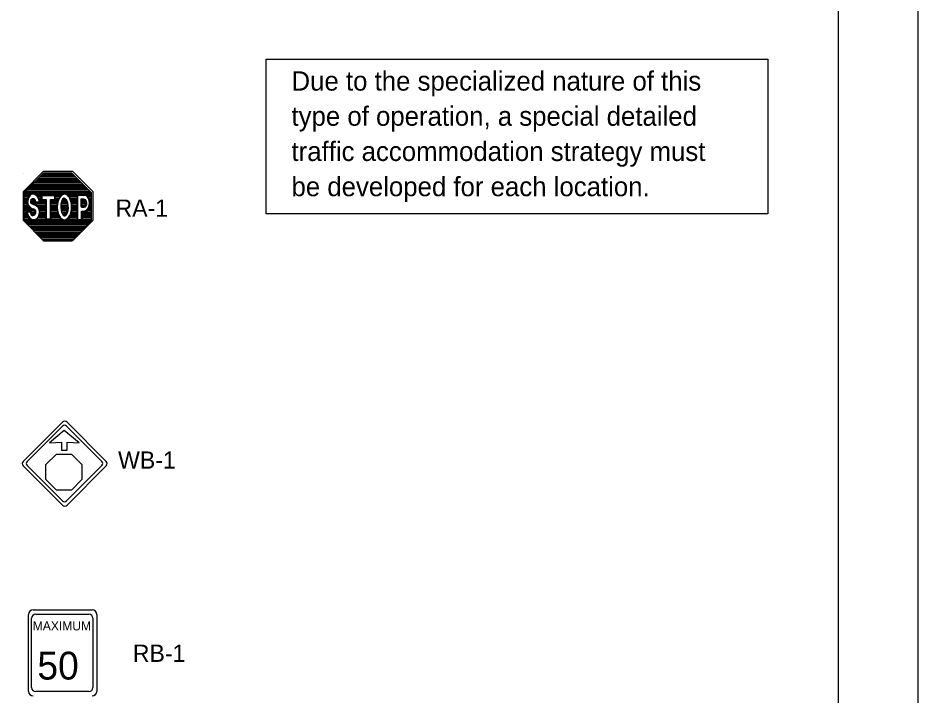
# Model space of a CAD drawing. Extents: x 1361 to 1577, y 123 to 402.
# Drawn here: x 1464.1 to 1577.1, y 208.6 to 293.6 of the extents above; entities that cross this region are included whole.
import ezdxf

# ---------------------------------------------------------------- set-up
doc = ezdxf.new("R2010")
doc.units = 0
for name, color, linetype in [('Level 10', 7, 'Continuous'), ('Level 44', 7, 'Continuous'), ('Level 60', 7, 'Continuous')]:
    doc.layers.add(name, color=color, linetype=linetype)

msp = doc.modelspace()

# ---------------------------------------------------------------- linework, layer by layer
at = {"layer": 'Level 10'}
for points in [[(1495.3, 288.49), (1558.27, 288.49), (1558.27, 269.05), (1495.3, 269.05)], [(1468.97, 238.93), (1470.85, 238.93), (1472.17, 237.6), (1472.17, 235.73), (1470.85, 234.41), (1468.97, 234.41), (1467.65, 235.73), (1467.65, 237.6)]]:
    msp.add_lwpolyline(points, close=True, dxfattribs=at)
at = {"layer": 'Level 44'}
for p, q in [((1467.36, 274.16), (1464.88, 271.69)), ((1464.88, 274.16), (1464.88, 274.16)), ((1470.88, 274.16), (1467.36, 274.16)), ((1473.35, 271.69), (1470.88, 274.16)), ((1464.88, 271.69), (1464.88, 268.17)), ((1467.06, 270.82), (1467.06, 271.38)), ((1467.06, 271.38), (1468.76, 271.38)), ((1467.12, 271.42), (1467.12, 270.88)), ((1468.76, 271.42), (1467.12, 271.42)), ((1468.76, 270.86), (1468.76, 271.42)), ((1468.76, 271.38), (1468.76, 270.81)), ((1469.96, 271.52), (1469.98, 271.52)), ((1472.44, 271.45), (1471.58, 271.45)), ((1471.58, 271.45), (1471.58, 268.35)), ((1471.66, 268.22), (1471.66, 271.41)), ((1471.66, 271.41), (1472.55, 271.41)), ((1473.35, 268.17), (1473.35, 271.69)), ((1466.8, 270.49), (1466.26, 270.49)), ((1466.86, 270.55), (1466.33, 270.55)), ((1467.65, 270.82), (1467.06, 270.82)), ((1467.12, 270.88), (1467.69, 270.88)), ((1467.65, 268.31), (1467.65, 270.82)), ((1467.69, 270.88), (1467.69, 268.44)), ((1468.76, 270.81), (1468.2, 270.81)), ((1468.2, 270.81), (1468.2, 268.31)), ((1468.22, 268.44), (1468.22, 270.86)), ((1468.22, 270.86), (1468.76, 270.86)), ((1469.94, 270.98), (1469.96, 270.99)), ((1472.36, 270.89), (1472.03, 270.89)), ((1472.03, 270.89), (1472.03, 269.99)), ((1472.03, 270.89), (1472.03, 269.99)), ((1472.36, 270.89), (1472.03, 270.89)), ((1472.12, 270.84), (1472.12, 269.91)), ((1472.47, 270.84), (1472.12, 270.84)), ((1472.47, 270.84), (1472.12, 270.84)), ((1472.12, 270.84), (1472.12, 269.91)), ((1465.18, 269.34), (1465.68, 269.34)), ((1465.29, 269.44), (1465.78, 269.44)), ((1472.03, 269.99), (1472.36, 269.99)), ((1472.03, 269.99), (1472.36, 269.99)), ((1472.09, 268.35), (1472.09, 269.41)), ((1472.09, 269.41), (1472.41, 269.41)), ((1472.12, 269.91), (1472.46, 269.91)), ((1472.12, 269.91), (1472.46, 269.91)), ((1472.19, 269.31), (1472.52, 269.31)), ((1472.19, 269.31), (1472.19, 268.22)), ((1472.51, 269.31), (1472.19, 269.31)), ((1464.88, 268.17), (1467.36, 265.69)), ((1465.34, 268.71), (1465.34, 268.71)), ((1468.2, 268.31), (1467.65, 268.31)), ((1467.69, 268.44), (1468.22, 268.44)), ((1470.88, 265.69), (1473.35, 268.17)), ((1471.58, 268.35), (1472.09, 268.35)), ((1472.19, 268.22), (1471.66, 268.22)), ((1467.36, 265.69), (1470.88, 265.69)), ((1469.72, 242.92), (1464.79, 238.01)), ((1475.21, 238.01), (1470.3, 242.92)), ((1465.29, 238), (1469.72, 242.43)), ((1469.95, 241.89), (1468.09, 240.32)), ((1471.81, 240.32), (1469.95, 241.89)), ((1470.24, 242.43), (1474.66, 238)), ((1468.09, 240.32), (1469.58, 240.4)), ((1469.58, 240.4), (1469.58, 239.41)), ((1470.32, 239.41), (1470.32, 240.4)), ((1470.32, 240.4), (1471.81, 240.32)), ((1469.58, 239.41), (1470.32, 239.41)), ((1464.5, 237.72), (1464.5, 237.72)), ((1464.79, 237.43), (1469.72, 232.5)), ((1464.8, 237.43), (1464.79, 237.43)), ((1469.72, 233.05), (1465.29, 237.48)), ((1474.66, 237.48), (1470.24, 233.05)), ((1470.3, 232.5), (1475.21, 237.43)), ((1466.04, 219.37), (1473.45, 219.37)), ((1465.47, 209.14), (1465.47, 218.8)), ((1465.85, 209.63), (1465.85, 218.32)), ((1466.36, 218.84), (1473.03, 218.84)), ((1473.55, 218.32), (1473.55, 209.63)), ((1474.02, 218.8), (1474.02, 209.14)), ((1465.47, 209.14), (1465.47, 209.14)), ((1465.85, 209.63), (1465.85, 209.63)), ((1473.03, 209.12), (1466.36, 209.12)), ((1466.17, 208.81), (1466.17, 208.81))]:
    msp.add_line(p, q, dxfattribs=at)
msp.add_lwpolyline([(1473.53, 268.24), (1470.98, 265.69), (1467.36, 265.69), (1464.81, 268.24), (1464.81, 271.87), (1467.36, 274.42), (1470.98, 274.42), (1473.53, 271.87)], close=True, dxfattribs=at)
for points in [[(1466.71, 273.52), (1471.52, 273.52)], [(1466.89, 273.7), (1471.34, 273.7)], [(1467.07, 273.87), (1471.16, 273.87)], [(1467.24, 274.05), (1470.99, 274.05)], [(1465.48, 272.29), (1472.75, 272.29)], [(1465.66, 272.46), (1472.58, 272.46)], [(1465.83, 272.64), (1472.4, 272.64)], [(1466.01, 272.81), (1472.22, 272.81)], [(1466.18, 272.99), (1472.05, 272.99)], [(1466.36, 273.17), (1471.87, 273.17)], [(1466.54, 273.34), (1471.69, 273.34)], [(1464.88, 271.58), (1473.35, 271.58)], [(1464.88, 271.41), (1465.7, 271.41)], [(1464.88, 271.23), (1465.55, 271.23)], [(1464.95, 271.76), (1473.28, 271.76)], [(1465.13, 271.93), (1473.1, 271.93)], [(1465.31, 272.11), (1472.93, 272.11)], [(1466.51, 271.41), (1467.12, 271.41)], [(1466.66, 271.23), (1467.12, 271.23)], [(1468.76, 271.41), (1469.58, 271.41)], [(1468.76, 271.23), (1469.42, 271.23)], [(1470.33, 271.41), (1471.58, 271.41)], [(1470.5, 271.23), (1471.58, 271.23)], [(1472.6, 271.41), (1473.35, 271.41)], [(1472.83, 271.23), (1473.35, 271.23)], [(1464.88, 271.05), (1465.45, 271.05)], [(1464.88, 270.88), (1465.4, 270.88)], [(1464.88, 270.7), (1465.37, 270.7)], [(1464.88, 270.52), (1465.36, 270.52)], [(1464.88, 270.35), (1465.38, 270.35)], [(1464.88, 270.17), (1465.43, 270.17)], [(1465.79, 270.7), (1466.34, 270.7)], [(1465.82, 270.52), (1467.69, 270.52)], [(1465.87, 270.88), (1466.26, 270.88)], [(1466.04, 270.35), (1467.69, 270.35)], [(1466.44, 270.17), (1467.69, 270.17)], [(1466.76, 271.05), (1467.12, 271.05)], [(1466.81, 270.88), (1467.12, 270.88)], [(1466.86, 270.7), (1467.69, 270.7)], [(1468.22, 270.7), (1469.16, 270.7)], [(1468.22, 270.52), (1469.12, 270.52)], [(1468.22, 270.35), (1469.09, 270.35)], [(1468.23, 270.17), (1469.07, 270.17)], [(1468.76, 271.05), (1469.3, 271.05)], [(1468.76, 270.88), (1469.22, 270.88)], [(1469.51, 270.17), (1470.4, 270.17)], [(1469.52, 270.35), (1470.38, 270.35)], [(1469.57, 270.52), (1470.34, 270.52)], [(1469.62, 270.7), (1470.28, 270.7)], [(1469.7, 270.88), (1470.19, 270.88)], [(1470.61, 271.05), (1471.58, 271.05)], [(1470.69, 270.88), (1471.58, 270.88)], [(1470.75, 270.7), (1471.58, 270.7)], [(1470.79, 270.52), (1471.58, 270.52)], [(1470.83, 270.35), (1471.58, 270.35)], [(1470.84, 270.17), (1471.58, 270.17)], [(1472.02, 270.35), (1472.65, 270.35)], [(1472.03, 270.88), (1472.43, 270.88)], [(1472.03, 270.7), (1472.6, 270.7)], [(1472.03, 270.52), (1472.65, 270.52)], [(1472.03, 270.17), (1472.6, 270.17)], [(1472.94, 271.05), (1473.35, 271.05)], [(1473.03, 270.88), (1473.35, 270.88)], [(1473.07, 270.7), (1473.35, 270.7)], [(1473.08, 270.17), (1473.35, 270.17)], [(1473.09, 270.52), (1473.35, 270.52)], [(1473.1, 270.35), (1473.35, 270.35)], [(1464.88, 270), (1465.54, 270)], [(1464.88, 269.82), (1465.77, 269.82)], [(1464.88, 269.64), (1466.18, 269.64)], [(1464.88, 269.47), (1466.37, 269.47)], [(1464.88, 269.29), (1465.31, 269.29)], [(1464.88, 269.12), (1465.35, 269.12)], [(1464.88, 268.94), (1465.4, 268.94)], [(1465.79, 269.29), (1466.39, 269.29)], [(1465.85, 269.12), (1466.35, 269.12)], [(1466.68, 270), (1467.69, 270)], [(1466.81, 269.82), (1467.69, 269.82)], [(1466.82, 268.94), (1467.69, 268.94)], [(1466.86, 269.64), (1467.69, 269.64)], [(1466.88, 269.12), (1467.69, 269.12)], [(1466.89, 269.47), (1467.69, 269.47)], [(1466.89, 269.29), (1467.69, 269.29)], [(1468.22, 270), (1469.06, 270)], [(1468.22, 269.82), (1469.06, 269.82)], [(1468.22, 269.64), (1469.07, 269.64)], [(1468.22, 269.47), (1469.1, 269.47)], [(1468.22, 269.29), (1469.12, 269.29)], [(1468.22, 269.12), (1469.17, 269.12)], [(1468.22, 268.94), (1469.24, 268.94)], [(1469.5, 270), (1470.4, 270)], [(1469.5, 269.82), (1470.41, 269.82)], [(1469.52, 269.64), (1470.39, 269.64)], [(1469.55, 269.47), (1470.36, 269.47)], [(1469.61, 269.29), (1470.31, 269.29)], [(1469.69, 269.12), (1470.21, 269.12)], [(1470.65, 268.94), (1471.58, 268.94)], [(1470.72, 269.12), (1471.58, 269.12)], [(1470.77, 269.29), (1471.58, 269.29)], [(1470.81, 269.47), (1471.58, 269.47)], [(1470.84, 269.64), (1471.58, 269.64)], [(1470.85, 269.82), (1471.58, 269.82)], [(1470.86, 270), (1471.58, 270)], [(1472.09, 269.29), (1473.35, 269.29)], [(1472.09, 269.12), (1473.35, 269.12)], [(1472.09, 268.94), (1473.35, 268.94)], [(1472.6, 269.47), (1473.35, 269.47)], [(1472.84, 269.64), (1473.35, 269.64)], [(1472.96, 269.82), (1473.35, 269.82)], [(1473.03, 270), (1473.35, 270)], [(1464.88, 268.76), (1465.49, 268.76)], [(1464.88, 268.59), (1465.63, 268.59)], [(1464.88, 268.41), (1465.83, 268.41)], [(1464.88, 268.24), (1473.35, 268.24)], [(1464.99, 268.06), (1473.24, 268.06)], [(1465.16, 267.88), (1473.07, 267.88)], [(1466.38, 268.41), (1469.67, 268.41)], [(1466.61, 268.59), (1467.69, 268.59)], [(1466.74, 268.76), (1467.69, 268.76)], [(1468.22, 268.76), (1469.33, 268.76)], [(1468.22, 268.59), (1469.45, 268.59)], [(1470.22, 268.41), (1471.58, 268.41)], [(1470.43, 268.59), (1471.58, 268.59)], [(1470.56, 268.76), (1471.58, 268.76)], [(1472.09, 268.76), (1473.35, 268.76)], [(1472.09, 268.59), (1473.35, 268.59)], [(1472.09, 268.41), (1473.35, 268.41)], [(1465.34, 267.71), (1472.89, 267.71)], [(1465.52, 267.53), (1472.72, 267.53)], [(1465.69, 267.36), (1472.54, 267.36)], [(1465.87, 267.18), (1472.36, 267.18)], [(1466.04, 267), (1472.19, 267)], [(1466.22, 266.83), (1472.01, 266.83)], [(1466.4, 266.65), (1471.84, 266.65)], [(1466.57, 266.48), (1471.66, 266.48)], [(1466.75, 266.3), (1471.48, 266.3)], [(1466.92, 266.12), (1471.31, 266.12)], [(1467.11, 265.95), (1471.13, 265.95)], [(1467.28, 265.77), (1470.95, 265.77)]]:
    msp.add_lwpolyline(points, dxfattribs=at)
for centre, radius, start, end in [((1466.24, 270.64), 0.967, 123.3662, 155.6734), ((1466.32, 270.7), 0.939, 123.3662, 155.6734), ((1466.02, 270.95), 0.591, 46.1369, 121.3987), ((1466.1, 271), 0.574, 46.1369, 121.3987), ((1465.77, 270.62), 0.998, 14.564, 49.0063), ((1465.86, 270.68), 0.968, 14.564, 49.0063), ((1472.4, 270.94), 0.515, 44.8528, 85.0441), ((1472.5, 270.89), 0.53, 44.8528, 85.0441), ((1472.23, 270.71), 0.79, 29.2241, 48.5308), ((1472.23, 270.71), 0.79, 29.2241, 48.5308), ((1472.34, 270.65), 0.814, 29.2241, 48.5308), ((1472.34, 270.65), 0.814, 29.2241, 48.5308), ((1466.44, 270.49), 1.19, 174.8171, 195.9183), ((1466.61, 270.53), 1.35, 157.7332, 177.1392), ((1466.1, 270.45), 0.847, 200.4481, 235.1107), ((1466.68, 270.59), 1.31, 157.7332, 177.1392), ((1466.51, 270.55), 1.16, 174.8171, 195.9183), ((1466.18, 270.52), 0.822, 200.4481, 235.1107), ((1465.96, 270.59), 0.268, 164.131, 238.1476), ((1465.99, 270.64), 0.294, 113.8064, 172.2407), ((1466.04, 270.65), 0.261, 164.131, 238.1476), ((1466.07, 270.69), 0.285, 113.8064, 172.2407), ((1466.8, 271.95), 1.87, 237.9816, 250.979), ((1465.97, 270.61), 0.308, 47.3017, 109.0119), ((1466.86, 271.97), 1.81, 237.9816, 250.979), ((1466.05, 270.67), 0.298, 47.3017, 109.0119), ((1465.82, 270.56), 0.449, 350.4412, 39.3244), ((1465.71, 268.97), 1.31, 46.2465, 67.9263), ((1465.91, 270.62), 0.436, 350.4412, 39.3244), ((1465.8, 269.08), 1.27, 46.2465, 67.9263), ((1465.42, 270.47), 1.38, 0.6952, 17.1452), ((1465.52, 270.53), 1.34, 0.6952, 17.1451), ((1472.29, 270.33), 0.35, 281.9191, 325.7868), ((1472.29, 270.33), 0.35, 281.9191, 325.7868), ((1472.31, 270.6), 0.306, 35.1198, 79.3117), ((1472.31, 270.6), 0.306, 35.1198, 79.3117), ((1472.39, 270.26), 0.361, 281.9191, 325.7868), ((1472.39, 270.26), 0.361, 281.9191, 325.7868), ((1472.42, 270.54), 0.315, 35.1198, 79.3117), ((1472.42, 270.54), 0.315, 35.1198, 79.3117), ((1472.17, 270.51), 0.475, 8.6031, 34.217), ((1472.17, 270.51), 0.475, 8.6031, 34.217), ((1472.2, 270.39), 0.45, 326.5086, 357.0313), ((1472.2, 270.39), 0.45, 326.5086, 357.0313), ((1472.15, 270.45), 0.504, 350.3416, 15.2342), ((1472.15, 270.45), 0.504, 350.3416, 15.2342), ((1472.27, 270.44), 0.489, 8.6031, 34.217), ((1472.27, 270.44), 0.489, 8.6031, 34.217), ((1472.3, 270.32), 0.464, 326.5086, 357.0313), ((1472.3, 270.32), 0.464, 326.5086, 357.0313), ((1472.25, 270.38), 0.52, 350.3417, 15.2342), ((1472.25, 270.38), 0.52, 350.3417, 15.2342), ((1472.22, 270.64), 0.839, 13.0674, 33.762), ((1471.4, 270.52), 1.71, 338.3153, 348.6699), ((1472.33, 270.58), 0.864, 13.0674, 33.762), ((1471.47, 270.39), 1.63, 3.3903, 15.6597), ((1471.79, 270.42), 1.31, 349.7521, 2.7916), ((1471.79, 270.42), 1.31, 349.7521, 2.7916), ((1471.48, 270.46), 1.76, 338.3153, 348.6699), ((1471.55, 270.32), 1.68, 3.3903, 15.6597), ((1471.88, 270.35), 1.35, 349.7521, 2.7916), ((1471.88, 270.35), 1.35, 349.7521, 2.7916), ((1466.85, 269.42), 1.67, 182.3841, 204.9519), ((1466.91, 269.51), 1.62, 182.3841, 204.9519), ((1468.26, 275.29), 6.13, 244.4624, 248.8312), ((1466.44, 269.34), 0.761, 179.0172, 193.5172), ((1466.08, 269.19), 0.382, 186.8728, 222.7449), ((1468.28, 275.21), 5.95, 244.4624, 248.8312), ((1466.51, 269.43), 0.739, 179.0171, 193.5172), ((1466.16, 269.29), 0.371, 186.8728, 222.7449), ((1466.03, 269.23), 0.372, 230.6966, 271.4573), ((1466.11, 269.33), 0.361, 230.6966, 271.4573), ((1466, 269.2), 0.345, 275.4374, 314.0625), ((1465.95, 269.2), 0.387, 34.2083, 74.1552), ((1466.09, 269.3), 0.335, 275.4374, 314.0625), ((1466.03, 269.3), 0.375, 34.2083, 74.1552), ((1465.85, 269.19), 0.459, 326.253, 358.7323), ((1465.96, 269.24), 0.355, 352.5761, 30.4776), ((1465.94, 269.3), 0.445, 326.253, 358.7323), ((1466.04, 269.34), 0.344, 352.5761, 30.4776), ((1465.36, 269.4), 1.51, 325.5092, 343.2894), ((1468.38, 271.36), 2.28, 219.479, 223.4261), ((1465.46, 269.5), 1.47, 325.5092, 343.2894), ((1468.39, 271.4), 2.21, 219.479, 223.426), ((1465.47, 269.26), 1.36, 5.9097, 21.9865), ((1465.57, 269.36), 1.32, 5.9097, 21.9865), ((1464.91, 269.27), 1.92, 351.247, 3.9864), ((1465.02, 269.37), 1.87, 351.247, 3.9864), ((1472.43, 269.59), 0.179, 259.7909, 293.5419), ((1472.28, 270.15), 0.761, 286.602, 299.809), ((1472.54, 269.5), 0.184, 259.7909, 293.5419), ((1472.38, 270.08), 0.784, 286.602, 299.8091), ((1472.43, 269.96), 0.515, 295.3838, 322.6188), ((1472.54, 269.87), 0.531, 295.3838, 322.6188), ((1472.21, 270.19), 0.835, 318.2922, 338.6031), ((1472.21, 270.19), 0.835, 318.2922, 338.6031), ((1472.31, 270.12), 0.86, 318.2922, 338.6031), ((1472.31, 270.12), 0.86, 318.2922, 338.6031), ((1466.39, 269.28), 1.19, 208.4154, 233.6553), ((1466.46, 269.38), 1.15, 208.4154, 233.6553), ((1466.02, 268.75), 0.544, 232.0536, 292.7397), ((1466.1, 268.86), 0.528, 232.0536, 292.7397), ((1465.89, 269.04), 0.868, 293.1413, 324.9906), ((1465.98, 269.15), 0.843, 293.1413, 324.9906), ((1470.01, 242.63), 0.412, 45, 135), ((1469.98, 242.17), 0.37, 45, 135), ((1465.09, 237.72), 0.412, 135, 225), ((1465.55, 237.74), 0.37, 135, 225), ((1474.4, 237.74), 0.37, 315, 45), ((1474.92, 237.72), 0.412, 315, 45), ((1469.98, 233.32), 0.37, 225, 315), ((1470.01, 232.8), 0.412, 225, 315), ((1466.04, 218.8), 0.572, 90, 180), ((1473.45, 218.8), 0.572, 360, 90), ((1466.36, 218.32), 0.514, 90, 180), ((1473.03, 218.32), 0.514, 360, 90), ((1466.04, 209.14), 0.572, 180, 270), ((1466.36, 209.63), 0.514, 180, 270), ((1473.03, 209.63), 0.514, 270, 360), ((1473.45, 209.14), 0.572, 270, 360)]:
    msp.add_arc(centre, radius, start, end, dxfattribs=at)
for centre, major_axis, ratio, start_param, end_param in [((1469.96, 269.94), (-0.01, -1.61), 0.558644, 3.185857, 9.451311), ((1469.99, 269.86), (-0.01, -1.66), 0.558644, 3.185857, 4.129398), ((1469.99, 269.86), (-0.01, -1.66), 0.558644, 0.656861, 3.168126), ((1469.99, 269.86), (-0.01, -1.66), 0.558644, 4.129576, 6.939747), ((1469.96, 269.98), (0.01, -1.05), 0.432619, 3.239639, 9.473919), ((1469.99, 269.9), (0.01, -1.09), 0.432619, 3.890436, 7.165085), ((1469.99, 269.9), (0.01, -1.09), 0.432619, 3.239639, 3.888884), ((1469.99, 269.9), (0.01, -1.09), 0.432619, 0.881967, 3.190734)]:
    msp.add_ellipse(centre, major_axis=major_axis, ratio=ratio, start_param=start_param, end_param=end_param, dxfattribs=at)
at = {"layer": 'Level 60'}
for points in [[(1361.11, 402.1), (1577.11, 402.1), (1577.11, 123.1), (1361.11, 123.1)], [(1380.24, 391.29), (1567.11, 391.29), (1567.11, 133.91), (1380.24, 133.91)]]:
    msp.add_lwpolyline(points, close=True, dxfattribs=at)

# ---------------------------------------------------------------- texts
at = {"layer": 'Level 10'}
for s, p in [('Due to the specialized nature of this ', (1498.47, 284.53)), ('type of operation, a special detailed ', (1498.47, 280.12)), ('traffic accommodation strategy must ', (1498.47, 275.7)), ('be developed for each location.', (1498.47, 271.28))]:
    msp.add_text(s, height=2.419, dxfattribs=at).set_placement(p)
for s, p in [('RA-1', (1476.38, 268.7)), ('WB-1', (1476.7, 237.09)), ('RB-1', (1478.55, 212.85))]:
    msp.add_text(s, height=2.165, rotation=360, dxfattribs=at).set_placement(p)
at = {"layer": 'Level 44'}
msp.add_text('MAXIMUM', height=1.133, rotation=360, dxfattribs=at).set_placement((1465.99, 216.8))
msp.add_text('50', height=3.494, dxfattribs=at).set_placement((1466.57, 210.63))

doc.saveas('drawing.dxf')
